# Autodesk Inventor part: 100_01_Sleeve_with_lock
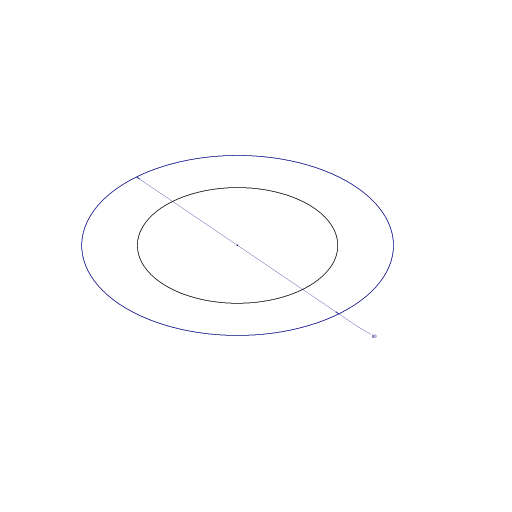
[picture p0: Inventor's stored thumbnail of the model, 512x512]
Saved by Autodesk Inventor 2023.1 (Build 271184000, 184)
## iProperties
Company: Fabian Stasiak CAD Consulting
Category: Autodesk® Inventor® Tutorial Series
Created: 2010-04
Part Number: 100_01_Sleeve_with_lock
Document SubType Name: Modeling
Designer: F.Stasiak
Density: 1 g/cm^3
Material: Ogólny
Appearance: Domyślna
Catalog Web Link: www.expertbooks.eu
Description: Sleeve with lock
Author: F.Stasiak
Subject: Sheet Metal Design. Basic and Advanced techniques
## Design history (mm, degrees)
sketch "Szkic1"
  geometry: C1 r 40 at (0, 0); C2 r 25.715 at (0, 0); 1 further point
  constraints: 2 centre point, 2 coincident
  dimensions: "d0" = 80 dimension on point (0, 0) C1.centre C1 C2.centre C2; "d0" = 80 diameter of C1
node "Bryła1"
